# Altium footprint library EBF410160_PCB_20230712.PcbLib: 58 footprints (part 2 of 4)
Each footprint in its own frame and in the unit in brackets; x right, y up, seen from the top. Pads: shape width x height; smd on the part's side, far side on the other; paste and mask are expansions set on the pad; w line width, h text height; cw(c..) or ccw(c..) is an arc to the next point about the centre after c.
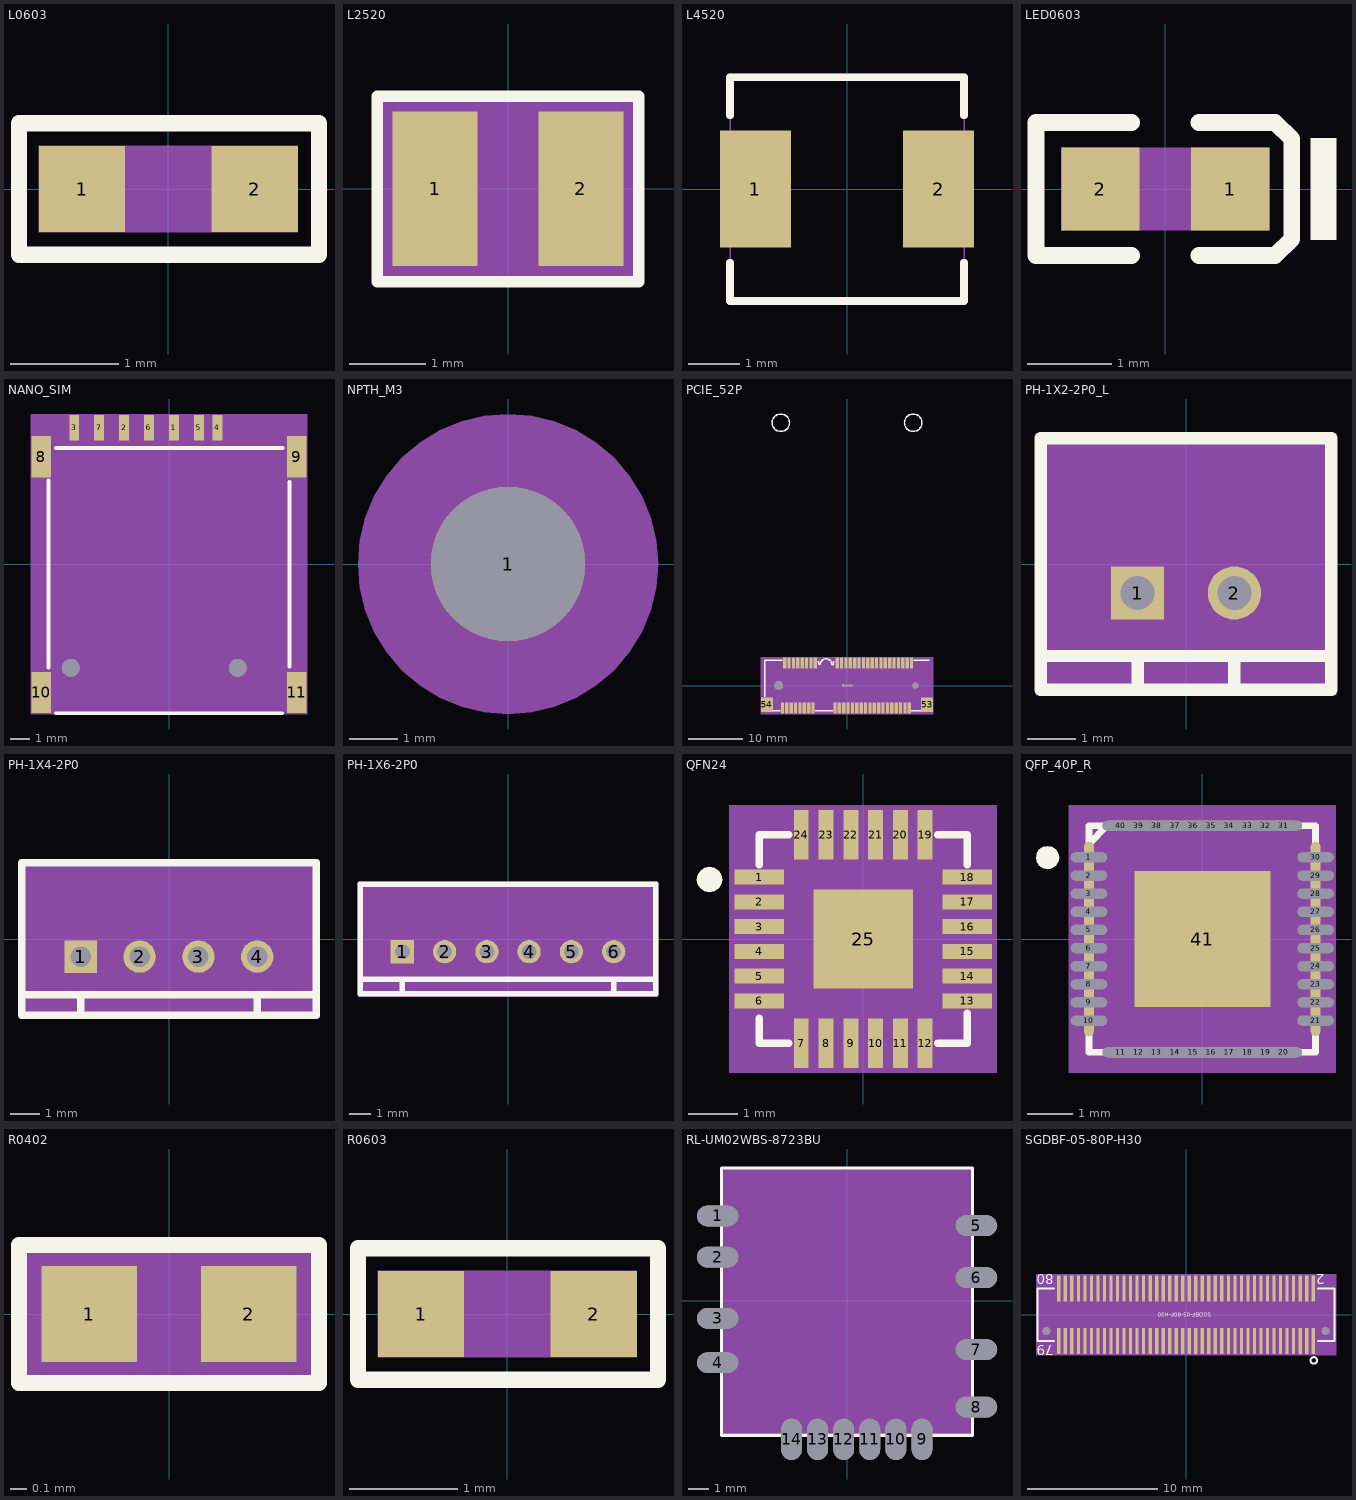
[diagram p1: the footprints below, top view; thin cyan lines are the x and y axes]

## L0603 [mil] "L0603"
pads (2):
  rect 31.5x31.5 smd: 1(-31.5,0) 2(31.5,0)
Top Overlay:
  lines w6: -54.5,-24 -54.5,24 55,24 55,-24 -54.5,-24
Top 3D Body:
  region: -47.24,-15.75 -47.24,15.75 47.24,15.75 47.24,-15.75
Mechanical 20:
  text "2" at 13.5,0 h45
  text "1" at -49.5,0 h45
3D body: height 150, standoff 0, extent -47.24,-15.75 47.24,15.75

## L2520 [mil] "L2520"
pads (2):
  rect 44x80 smd: 1(-37.75,0) 2(37.75,0)
Top Overlay:
  lines w6: -67.68,-48.15 -67.67,-48.15 67.67,-48.15 67.67,47.92 -67.68,47.92 -67.68,-48.15
Top 3D Body:
  region: -65,-45 65,-45 65,45 -65,45
Mechanical 20:
  text "2" at 37.75,-4.72 h11.81
  text "1" at -37.75,-4.72 h11.81
3D body: height 150, standoff 0, extent -65,-45 65,45

## L4520 [mm] "L4520"
pads (2):
  rect 1.4x2.3 smd: 1(-1.803,-0.002) 2(1.798,-0.002)
Top Overlay:
  lines w0.15: -2.302,-1.452 -2.302,-2.202 2.298,-2.202 2.298,-1.452 ; -2.302,1.448 -2.302,2.198 2.298,2.198 2.298,1.448
Top 3D Body:
  lines w0.025: -2.302,-2.202 2.303,-2.202 2.303,2.203 -2.302,2.203 -2.302,-2.202
Mechanical 20:
  text "1" at -1.803,-0.256 h0.64
  text "2" at 1.798,-0.256 h0.64
Top Assembly:
  lines w0.15: -2.302,-1.452 -2.302,-2.202 2.298,-2.202 2.298,-1.452 ; -2.302,1.448 -2.302,2.198 2.298,2.198 2.298,1.448

## LED0603 [mm] "LED0603"
pads (2):
  rect 0.93x0.98 smd: 1(0.77,0) 2(-0.77,0)
Top Overlay:
  dashed: 1.725,-0.6 2.025,-0.6 2.025,0.6 1.725,0.6
  lines w0.2: -0.4,-0.79 -1.535,-0.79 -1.535,0.79 -0.4,0.79 ; 0.4,-0.79 1.3,-0.79 1.5,-0.597 1.5,0.597 1.3,0.79 0.4,0.79
Top 3D Body:
  region: -1.235,-0.49 1.235,-0.49 1.235,0.49 -1.235,0.49
Mechanical 20:
  text "2" at -0.77,0.254 h0.64
  text "1" at 0.77,0.254 h0.64
3D body: height 3.81, standoff 0, extent -1.235,-0.49 1.235,0.49

## NANO_SIM [mm] "NANO_SIM"
pads (13):
  rect 0.5x1.3 smd: 1(0.25,6.94) 2(-2.29,6.94) 3(-4.83,6.94) 4(2.47,6.94) 5(1.52,6.94) 6(-1.02,6.94) 7(-3.56,6.94)
  rect 1x2.1 smd: 8(-6.5,5.46) 9(6.5,5.46) 10(-6.5,-6.54) 11(6.5,-6.54)
  round 0.9 hole 0.9 unplated: ""(-5,-5.29) ""(3.5,-5.29)
Top Overlay:
  lines w0.2: -6.145,-5.268 -6.145,4.247 ; -5.756,5.9 5.784,5.9 ; -5.749,-7.6 0,-7.6 5.749,-7.6 ; 6.145,-5.215 6.145,4.189
Top 3D Body:
  region: -7.05,-7.64 -7.05,7.64 7.05,7.64 7.05,-7.64
Mechanical 20:
  text "7" at -3.56,7.06 h0.3
  text "2" at -2.29,7.06 h0.3
  text "3" at -4.83,7.06 h0.3
  text "5" at 1.52,7.06 h0.3
  text "8" at -6.5,5.58 h0.3
  text "9" at 6.5,5.58 h0.3
  text "10" at -6.5,-6.3 h0.3
  text "11" at 6.5,-6.3 h0.3
  text "1" at 0.25,7.06 h0.3
  text "6" at -1.02,7.06 h0.3
  text "4" at 2.47,7.06 h0.3
3D body: height 3.81, standoff 0, extent -7.05,-7.64 7.05,7.64

## NPTH_M3 [mm] "NPTH_M3"
pads (1):
  round 3.2 / inner round 1.524 / far side round 3.2 hole 3.2 unplated: 1(0,0)
Top Overlay:
  text "NPTH_M3" at -0.757,0.766 h0.3
Top 3D Body:
  region: 3.11,0 3.071,0.486 2.957,0.961 2.771,1.412 2.516,1.828 2.199,2.199 1.828,2.516 1.412,2.771 0.961,2.957 0.486,3.071 0,3.11 -0.486,3.071 -0.961,2.957 -1.412,2.771 -1.551,2.686 -1.828,2.516 -2.199,2.199 -2.516,1.828 -2.771,1.412 -2.957,0.961 -3.071,0.486 -3.11,0 -3.071,-0.486 -2.957,-0.961 -2.771,-1.412 -2.516,-1.828 -2.199,-2.199 -1.828,-2.516 -1.551,-2.686 -1.412,-2.771 -0.961,-2.957 -0.486,-3.071 0,-3.11 0.486,-3.071 0.961,-2.957 1.412,-2.771 1.828,-2.516 2.199,-2.199 2.516,-1.828 2.771,-1.412 2.957,-0.961 3.071,-0.486
Mechanical 20:
  text "1" at -0.254,0 h0.64
3D body: height 3.81, standoff 0, extent -3.11,-3.11 3.11,3.11

## PCIE_52P [mm] "PCIE_52P"
pads (56):
  rect 0.6x2 smd: 1(-11.8,-4.1) 2(-11.4,4.1) 3(-11,-4.1) 4(-10.6,4.1) 5(-10.2,-4.1) 6(-9.8,4.1) 7(-9.4,-4.1) 8(-9,4.1) 9(-8.6,-4.1) 10(-8.2,4.1) 11(-7.8,-4.1) 12(-7.4,4.1) 13(-7,-4.1) 14(-6.6,4.1) 15(-6.2,-4.1) 16(-5.8,4.1) 17(-2.2,-4.1) 18(-1.8,4.1) 19(-1.4,-4.1) 20(-1,4.1) 21(-0.6,-4.1) 22(-0.2,4.1) 23(0.2,-4.1) 24(0.6,4.1) 25(1,-4.1) 26(1.4,4.1) 27(1.8,-4.1) 28(2.2,4.1) 29(2.6,-4.1) 30(3,4.1) 31(3.4,-4.1) 32(3.8,4.1) 33(4.2,-4.1) 34(4.6,4.1) 35(5,-4.1) 36(5.4,4.1) 37(5.8,-4.1) 38(6.2,4.1) 39(6.6,-4.1) 40(7,4.1) 41(7.4,-4.1) 42(7.8,4.1) 43(8.2,-4.1) 44(8.6,4.1) 45(9,-4.1) 46(9.4,4.1) 47(9.8,-4.1) 48(10.2,4.1) 49(10.6,-4.1) 50(11,4.1) 51(11.4,-4.1) 52(11.8,4.1)
  rect 2.15x2.6 smd: 53(14.65,-3.5) 54(-14.65,-3.5)
  round 1.6 hole 1.6 unplated: ""(-12.5,0)
  round 1.1 hole 1.1 unplated: ""(12.5,0)
Top Overlay:
  circle w0.25: c-12.1,48.049 r1.6
  circle w0.25: c12.1,48.049 r1.6
  lines w0.25: -15,-2.011 -15,4.6 -11.869,4.6 ; -13.487,-4.6 -12.194,-4.6 ; -5.803,-4.6 -2.572,-4.6 ; -5.325,4.387 -5.165,4.387 -5.165,3.883 -4.887,3.883 cw(c-3.843,3.859) -2.8,3.859 -2.8,3.847 -2.474,3.847 -2.474,4.381 -2.29,4.381 ; 11.787,-4.6 13.477,-4.6 ; 12.237,4.6 15,4.6
  text "MINI-PCIE" at 1.097,0.152 h0.3
Top 3D Body:
  region: -15.8,-5.2 -15.8,5.2 15.8,5.2 15.8,-5.2
Mechanical 20:
  text "14" at -6.121,4.1 h0.3
  text "22" at 0.28,4.1 h0.3
  text "10" at -7.72,4.1 h0.3
  text "33" at 4.68,-4.1 h0.3
  text "1" at -11.56,-4.1 h0.3
  text "7" at -9.16,-4.1 h0.3
  text "31" at 3.88,-4.1 h0.3
  text "20" at -0.52,4.1 h0.3
  text "12" at -6.92,4.1 h0.3
  text "25" at 1.48,-4.1 h0.3
  text "23" at 0.68,-4.1 h0.3
  text "11" at -7.32,-4.1 h0.3
  text "13" at -6.521,-4.1 h0.3
  text "50" at 11.48,4.1 h0.3
  text "40" at 7.48,4.1 h0.3
  text "34" at 5.08,4.1 h0.3
  text "26" at 1.88,4.1 h0.3
  text "18" at -1.32,4.1 h0.3
  text "4" at -10.36,4.1 h0.3
  text "43" at 8.68,-4.1 h0.3
  text "37" at 6.279,-4.1 h0.3
  text "35" at 5.48,-4.1 h0.3
  text "29" at 3.08,-4.1 h0.3
  text "27" at 2.28,-4.1 h0.3
  text "21" at -0.12,-4.1 h0.3
  text "15" at -5.72,-4.1 h0.3
  text "9" at -8.36,-4.1 h0.3
  text "54" at -14.17,-3.5 h0.3
  text "53" at 15.13,-3.5 h0.3
  text "8" at -8.76,4.1 h0.3
  text "41" at 7.88,-4.1 h0.3
  text "39" at 7.08,-4.1 h0.3
  text "52" at 12.28,4.1 h0.3
  text "24" at 1.08,4.1 h0.3
  text "2" at -11.16,4.1 h0.3
  text "32" at 4.28,4.1 h0.3
  text "19" at -0.92,-4.1 h0.3
  text "44" at 9.08,4.1 h0.3
  text "46" at 9.88,4.1 h0.3
  text "30" at 3.48,4.1 h0.3
  text "28" at 2.68,4.1 h0.3
  text "5" at -9.96,-4.1 h0.3
  text "16" at -5.32,4.1 h0.3
  text "17" at -1.72,-4.1 h0.3
  text "51" at 11.88,-4.1 h0.3
  text "49" at 11.08,-4.1 h0.3
  text "47" at 10.28,-4.1 h0.3
  text "45" at 9.48,-4.1 h0.3
  text "48" at 10.68,4.1 h0.3
  text "6" at -9.56,4.1 h0.3
  text "3" at -10.76,-4.1 h0.3
  text "42" at 8.28,4.1 h0.3
  text "36" at 5.88,4.1 h0.3
  text "38" at 6.679,4.1 h0.3
Top Assembly:
  dashed: -15.8,5.2 -15.8,-5.2 15.8,-5.2 15.8,5.2
3D body: height 3.81, standoff 0, extent -15.8,-5.2 15.8,5.2

## PH-1X2-2P0_L [mm] "PH-1X2-2P0_L"
pads (2):
  rect 1.1x1.1 / inner round 1.524 / far side rect 1.1x1.1 hole 0.7: 1(-1,-0.6)
  round 1.1 / inner round 1.524 / far side round 1.1 hole 0.7: 2(1,-0.6)
Top Overlay:
  lines w0.254: -3,-1.9 3,-1.9 ; -1,-2.6 -1,-1.9 ; 1,-2.6 1,-1.9 ; -3,-2.6 3,-2.6 3,2.6 -3,2.6 -3,-2.6
Bottom Overlay:
  lines w0.6: 0,-1.1 0,-0.1
Top 3D Body:
  region: -3.1,2.7 -3.1,-2.7 3.1,-2.7 3.1,2.7
Mechanical 20:
  text "1" at -1.254,-0.6 h0.64
  text "2" at 0.746,-0.6 h0.64
Top Assembly:
  lines w0.025: -3.1,-2.7 3.1,-2.7 3.1,2.7 -3.1,2.7 -3.1,-2.7
3D body: height 3.81, standoff 0, extent -3.1,-2.7 3.1,2.7

## PH-1X4-2P0 [mm] "PH-1X4-2P0"
pads (4):
  rect 1.1x1.1 / inner round 1.524 / far side rect 1.1x1.1 hole 0.7: 1(-3,-0.6)
  round 1.1 / inner round 1.524 / far side round 1.1 hole 0.7: 2(-1,-0.6) 3(1,-0.6)
  round 1.1 hole 0.7: 4(3,-0.6)
Top Overlay:
  lines w0.254: -5,-1.9 5,-1.9 ; -3,-2.6 -3,-1.9 ; 3,-2.6 3,-1.9 ; -5,-2.6 5,-2.6 5,2.6 -5,2.6 -5,-2.6
Top 3D Body:
  region: -5.1,2.7 -5.1,-2.7 5.1,-2.7 5.1,2.7
Mechanical 20:
  text "4" at 2.594,-0.6 h1.02
  text "1" at -3.406,-0.6 h1.02
  text "2" at -1.406,-0.6 h1.02
  text "3" at 0.594,-0.6 h1.02
3D body: height 3.81, standoff 0, extent -5.1,-2.7 5.1,2.7

## PH-1X6-2P0 [mm] "PH-1X6-2P0"
pads (6):
  rect 1.1x1.1 / inner round 1.524 / far side rect 1.1x1.1 hole 0.7: 1(-5,-0.6)
  round 1.1 hole 0.7: 2(-3,-0.6) 4(1,-0.6) 6(5,-0.6)
  round 1.1 / inner round 1.524 / far side round 1.1 hole 0.7: 3(-1,-0.6) 5(3,-0.6)
Top Overlay:
  lines w0.254: -7,-1.9 7,-1.9 ; -5,-2.6 -5,-1.9 ; 5,-2.6 5,-1.9 ; -7,-2.6 -7,2.6 7,2.6 7,-2.6 -7,-2.6
Bottom Overlay:
  lines w0.5: -4,-1.1 -4,-0.1 ; -2,-1.1 -2,-0.1 ; 0,-1.1 0,-0.1 ; 2,-1.1 2,-0.1 ; 4,-1.1 4,-0.1
Top 3D Body:
  region: -7.1,2.7 -7.1,-2.7 7.1,-2.7 7.1,2.7
Mechanical 20:
  text "5" at 3,-0.854 h0.64
  text "1" at -5,-0.854 h0.64
  text "2" at -3,-0.854 h0.64
  text "4" at 1,-0.854 h0.64
  text "6" at 5,-0.854 h0.64
  text "3" at -1,-0.854 h0.64
Top Assembly:
  lines w0.025: -7.1,-2.7 7.1,-2.7 7.1,2.7 -7.1,2.7 -7.1,-2.7
3D body: height 3.81, standoff 0, extent -7.1,-2.7 7.1,2.7

## QFN24 [mm] "QFN24"
pads (25):
  rect 1x0.3 smd: 1(-2.1,1.25) 2(-2.1,0.75) 3(-2.1,0.25) 4(-2.1,-0.25) 5(-2.1,-0.75) 6(-2.1,-1.25) 13(2.1,-1.25) 14(2.1,-0.75) 15(2.1,-0.25) 16(2.1,0.25) 17(2.1,0.75) 18(2.1,1.25)
  rect 0.3x1 smd: 7(-1.25,-2.1) 8(-0.75,-2.1) 9(-0.25,-2.1) 10(0.25,-2.1) 11(0.75,-2.1) 12(1.25,-2.1) 19(1.25,2.1) 20(0.75,2.1) 21(0.25,2.1) 22(-0.25,2.1) 23(-0.75,2.1) 24(-1.25,2.1)
  rect 2x2 smd: 25(0,0)
Top Overlay:
  dashed: -3.1,1.455 -3.198,1.435 -3.28,1.38 -3.335,1.298 -3.355,1.2 -3.335,1.102 -3.317,1.075 -3.28,1.02 -3.198,0.965 -3.1,0.945 -3.002,0.965 -2.92,1.02 -2.883,1.075 -2.865,1.102 -2.845,1.2 -2.865,1.298 -2.92,1.38 -3.002,1.435
  lines w0.15: -2.1,-1.6 -2.1,-2.1 -1.5,-2.1 ; -2.1,1.5 -2.1,2.1 -1.5,2.1 ; 1.5,-2.1 2.1,-2.1 2.1,-1.5 ; 1.5,2.1 2.1,2.1 2.1,1.5
Top 3D Body:
  region: -2.7,-2.7 2.7,-2.7 2.7,2.7 -2.7,2.7
Mechanical 20:
  text "16" at 2.1,-0.055 h0.38
  text "4" at -2.1,-0.402 h0.38
  text "20" at 0.75,1.795 h0.38
  text "1" at -2.1,1.098 h0.38
  text "3" at -2.1,0.098 h0.38
  text "18" at 2.1,0.945 h0.38
  text "8" at -0.75,-2.252 h0.38
  text "6" at -2.1,-1.402 h0.38
  text "12" at 1.25,-2.405 h0.38
  text "5" at -2.1,-0.902 h0.38
  text "10" at 0.25,-2.405 h0.38
  text "7" at -1.25,-2.252 h0.38
  text "15" at 2.1,-0.555 h0.38
  text "9" at -0.25,-2.252 h0.38
  text "14" at 2.1,-1.055 h0.38
  text "11" at 0.75,-2.405 h0.38
  text "25" at 0,-0.305 h0.38
  text "19" at 1.25,1.795 h0.38
  text "24" at -1.25,1.795 h0.38
  text "17" at 2.1,0.445 h0.38
  text "2" at -2.1,0.598 h0.38
  text "21" at 0.25,1.795 h0.38
  text "13" at 2.1,-1.555 h0.38
  text "23" at -0.75,1.795 h0.38
  text "22" at -0.25,1.795 h0.38
Top Assembly:
  lines w0.2: -2.05,-2.05 2.05,-2.05 2.05,2.05 -2.05,2.05 -2.05,-2.05
3D body: height 3.81, standoff 0, extent -2.7,-2.7 2.7,2.7

## QFP_40P_R [mil] "QFP_40P_R"
pads (41):
  oval 8.66x27.17 smd: 1(-98.43,70.87) 2(-98.43,55.12) 3(-98.43,39.37) 4(-98.43,23.62) 5(-98.43,7.87) 6(-98.43,-7.87) 7(-98.43,-23.62) 8(-98.43,-39.37) 9(-98.43,-55.12) 10(-98.43,-70.87) 21(98.43,-70.87) 22(98.43,-55.12) 23(98.43,-39.37) 24(98.43,-23.62) 25(98.43,-7.87) 26(98.43,7.87) 27(98.43,23.62) 28(98.43,39.37) 29(98.43,55.12) 30(98.43,70.87)
  oval 27.17x8.66 smd: 11(-70.87,-98.43) 12(-55.12,-98.43) 13(-39.37,-98.43) 14(-23.62,-98.43) 15(-7.87,-98.43) 16(7.87,-98.43) 17(23.62,-98.43) 18(39.37,-98.43) 19(55.12,-98.43) 20(70.87,-98.43) 31(70.87,98.43) 32(55.12,98.43) 33(39.37,98.43) 34(23.62,98.43) 35(7.87,98.43) 36(-7.87,98.43) 37(-23.62,98.43) 38(-39.37,98.43) 39(-55.12,98.43) 40(-70.87,98.43)
  rect 118.11x118.11 smd: 41(0,0)
Top Overlay:
  dashed: -127.25,77.81 -130.51,79.98 -134.35,80.75 -138.19,79.98 -141.45,77.81 -143.62,74.55 -143.88,73.26 -144.39,70.71 -143.62,66.87 -141.45,63.62 -138.19,61.44 -134.35,60.68 -131.8,61.18 -130.51,61.44 -127.25,63.62 -125.08,66.87 -124.32,70.71 -125.08,74.55
  lines w1: -98.43,-98.43 -98.43,98.43 98.43,98.43 98.43,-98.43 -98.43,-98.43
  lines w5.91: -98.43,-82.68 -98.43,-98.43 -82.68,-98.43 ; 82.68,-98.43 98.43,-98.43 98.43,-82.68 ; 82.68,98.43 98.43,98.43 98.43,82.68 ; -98.43,82.68 -82.68,98.43 -98.43,98.43 -98.43,82.68
Top Courtyard:
  dashed: -116.14,-116.14 116.14,-116.14 116.14,116.14 -116.14,116.14
Top 3D Body:
  region: -116.14,-116.14 116.14,-116.14 116.14,116.14 -116.14,116.14
Mechanical 20:
  text "21" at 87.11,-82.18 h20
  text "38" at -50.68,87.12 h20
  text "8" at -104.09,-45.03 h20
  text "3" at -104.09,33.71 h20
  text "1" at -104.09,65.21 h20
  text "2" at -104.09,49.46 h20
  text "4" at -104.09,17.96 h20
  text "5" at -104.09,2.21 h20
  text "6" at -104.09,-13.53 h20
  text "7" at -104.09,-29.27 h20
  text "9" at -104.09,-60.77 h20
  text "10" at -109.74,-82.18 h20
  text "30" at 87.11,59.56 h20
  text "18" at 28.06,-109.74 h20
  text "17" at 12.3,-109.74 h20
  text "16" at -3.44,-109.74 h20
  text "15" at -19.18,-109.74 h20
  text "19" at 43.8,-109.74 h20
  text "31" at 59.56,87.11 h20
  text "36" at -19.18,87.12 h20
  text "37" at -34.93,87.11 h20
  text "32" at 43.8,87.12 h20
  text "41" at -11.31,-11.31 h20
  text "33" at 28.06,87.12 h20
  text "34" at 12.3,87.11 h20
  text "13" at -50.68,-109.74 h20
  text "20" at 59.56,-109.74 h20
  text "14" at -34.93,-109.74 h20
  text "25" at 87.12,-19.18 h20
  text "39" at -66.43,87.12 h20
  text "24" at 87.11,-34.93 h20
  text "23" at 87.12,-50.68 h20
  text "22" at 87.12,-66.43 h20
  text "27" at 87.11,12.3 h20
  text "26" at 87.12,-3.44 h20
  text "29" at 87.12,43.8 h20
  text "40" at -82.18,87.11 h20
  text "11" at -82.18,-109.74 h20
  text "28" at 87.12,28.06 h20
  text "12" at -66.43,-109.74 h20
  text "35" at -3.44,87.12 h20
Top Assembly:
  lines w1: -98.43,90.55 -90.55,98.43 ; -98.43,-98.43 -98.43,98.43 98.43,98.43 98.43,-98.43 -98.43,-98.43
3D body: height 150, standoff 0, extent -116.14,-116.14 116.14,116.14

## R0402 [mm] "R0402"
pads (2):
  rect 0.599x0.599 smd: 1(-0.5,0) 2(0.5,0)
Top Overlay:
  lines w0.102: -0.94,-0.432 -0.94,0.432 0.94,0.432 0.94,-0.432 -0.94,-0.432
Top 3D Body:
  region: 0.94,0.432 0.94,-0.432 -0.94,-0.432 -0.94,0.432
Mechanical 20:
  text "2" at 0.246,0 h0.64
  text "1" at -0.754,0 h0.64
Top Assembly:
  dashed: -0.94,-0.432 -0.94,0.432 0.94,0.432 0.94,-0.432
3D body: height 3.81, standoff 0, extent -0.94,-0.432 0.94,0.432

## R0603 [mil] "R0603"
pads (2):
  rect 31.5x31.5 smd: 1(-31.5,0) 2(31.5,0)
Top Overlay:
  lines w6: -54.5,-24 -54.5,24 55,24 55,-24 -54.5,-24
Top 3D Body:
  region: -47.24,-15.75 -47.24,15.75 47.24,15.75 47.24,-15.75
Mechanical 20:
  text "2" at 31.5,18 h45
  text "1" at -31.5,18 h45
3D body: height 150, standoff 0, extent -47.24,-15.75 47.24,15.75

## RL-UM02WBS-8723BU [mm] "RL-UM02WBS-8723BU"
pads (14):
  oval 2x1 smd: 1(-6.3,4.122) 2(-6.3,2.122) 3(-6.3,-0.858) 4(-6.3,-3.018) 5(6.3,3.652) 6(6.3,1.122) 7(6.3,-2.378) 8(6.3,-5.178)
  oval 1x2 smd: 9(3.65,-6.748) 10(2.38,-6.748) 11(1.11,-6.748) 12(-0.16,-6.748) 13(-1.43,-6.748) 14(-2.7,-6.748)
Top Overlay:
  lines w0.15: -6.1,-6.548 -6.1,6.452 6.1,6.452 6.1,-6.548 -6.1,-6.548
Top 3D Body:
  region: -6.096,-6.452 6.096,-6.452 6.096,6.452 -6.096,6.452
Mechanical 20:
  text "5" at 6.554,3.652 h0.64
  text "1" at -6.046,4.122 h0.64
  text "8" at 6.554,-5.178 h0.64
  text "2" at -6.046,2.122 h0.64
  text "7" at 6.554,-2.378 h0.64
  text "6" at 6.554,1.122 h0.64
  text "4" at -6.046,-3.018 h0.64
  text "10" at 2.888,-6.748 h0.64
  text "9" at 3.904,-6.748 h0.64
  text "3" at -6.046,-0.858 h0.64
  text "12" at 0.348,-6.748 h0.64
  text "13" at -0.922,-6.748 h0.64
  text "14" at -2.192,-6.748 h0.64
  text "11" at 1.618,-6.748 h0.64
3D body: height 3.81, standoff 0, extent -6.096,-6.452 6.096,6.452

## SGDBF-05-80P-H30 [mm] "SGDBF-05-80P-H30"
pads (82):
  rect 0.25x2 smd: 1(9.75,-2) 2(9.75,2) 3(9.25,-2) 4(9.25,2) 5(8.75,-2) 6(8.75,2) 7(8.25,-2) 8(8.25,2) 9(7.75,-2) 10(7.75,2) 11(7.25,-2) 12(7.25,2) 13(6.75,-2) 14(6.75,2) 15(6.25,-2) 16(6.25,2) 17(5.75,-2) 18(5.75,2) 19(5.25,-2) 20(5.25,2) 21(4.75,-2) 22(4.75,2) 23(4.25,-2) 24(4.25,2) 25(3.75,-2) 26(3.75,2) 27(3.25,-2) 28(3.25,2) 29(2.75,-2) 30(2.75,2) 31(2.25,-2) 32(2.25,2) 33(1.75,-2) 34(1.75,2) 35(1.25,-2) 36(1.25,2) 37(0.75,-2) 38(0.75,2) 39(0.25,-2) 40(0.25,2) 41(-0.25,-2) 42(-0.25,2) 43(-0.75,-2) 44(-0.75,2) 45(-1.25,-2) 46(-1.25,2) 47(-1.75,-2) 48(-1.75,2) 49(-2.25,-2) 50(-2.25,2) 51(-2.75,-2) 52(-2.75,2) 53(-3.25,-2) 54(-3.25,2) 55(-3.75,-2) 56(-3.75,2) 57(-4.25,-2) 58(-4.25,2) 59(-4.75,-2) 60(-4.75,2) 61(-5.25,-2) 62(-5.25,2) 63(-5.75,-2) 64(-5.75,2) 65(-6.25,-2) 66(-6.25,2) 67(-6.75,-2) 68(-6.75,2) 69(-7.25,-2) 70(-7.25,2) 71(-7.75,-2) 72(-7.75,2) 73(-8.25,-2) 74(-8.25,2) 75(-8.75,-2) 76(-8.75,2) 77(-9.25,-2) 78(-9.25,2) 79(-9.75,-2) 80(-9.75,2)
  round 0.6 hole 0.6 unplated: ""(-10.7,-1.25) ""(10.7,-1.25)
Top Overlay:
  circle w0.15: c9.8,-3.5 r0.25
  lines w0.15: -10.1,-2 -11.4,-2 -11.4,2 -10.1,2 ; 10.1,-2 11.4,-2 11.4,2 10.1,2
  text "79" at -10.132,-2.356 h0.76
  text "2" at 10.62,3.105 h0.76
  text "80" at -10.132,3.105 h0.76
  text "SGDBF-05-80P-H30" at 1.951,0.152 h0.3
Top 3D Body:
  region: 11.5,-3.1 11.5,3.1 -11.5,3.1 -11.5,-3.1
Mechanical 20:
  text "34" at 2.258,2 h0.64
  text "32" at 2.758,2 h0.64
  text "28" at 3.758,2 h0.64
  text "36" at 1.758,2 h0.64
  text "38" at 1.258,2 h0.64
  text "45" at -0.742,-2 h0.64
  text "52" at -2.242,2 h0.64
  text "50" at -1.742,2 h0.64
  text "48" at -1.242,2 h0.64
  text "46" at -0.742,2 h0.64
  text "42" at 0.258,2 h0.64
  text "27" at 3.758,-2 h0.64
  text "25" at 4.258,-2 h0.64
  text "51" at -2.242,-2 h0.64
  text "53" at -2.742,-2 h0.64
  text "10" at 8.258,2 h0.64
  text "49" at -1.742,-2 h0.64
  text "15" at 6.758,-2 h0.64
  text "61" at -4.742,-2 h0.64
  text "29" at 3.258,-2 h0.64
  text "13" at 7.258,-2 h0.64
  text "8" at 8.504,2 h0.64
  text "31" at 2.758,-2 h0.64
  text "47" at -1.242,-2 h0.64
  text "17" at 6.258,-2 h0.64
  text "37" at 1.258,-2 h0.64
  text "59" at -4.242,-2 h0.64
  text "39" at 0.758,-2 h0.64
  text "11" at 7.758,-2 h0.64
  text "72" at -7.242,2 h0.64
  text "74" at -7.742,2 h0.64
  text "1" at 10.004,-2 h0.64
  text "23" at 4.758,-2 h0.64
  text "33" at 2.258,-2 h0.64
  text "69" at -6.742,-2 h0.64
  text "71" at -7.242,-2 h0.64
  text "73" at -7.742,-2 h0.64
  text "75" at -8.242,-2 h0.64
  text "77" at -8.742,-2 h0.64
  text "79" at -9.242,-2 h0.64
  text "2" at 10.004,2 h0.64
  text "12" at 7.758,2 h0.64
  text "26" at 4.258,2 h0.64
  text "40" at 0.758,2 h0.64
  text "54" at -2.742,2 h0.64
  text "58" at -3.742,2 h0.64
  text "64" at -5.242,2 h0.64
  text "70" at -6.742,2 h0.64
  text "76" at -8.242,2 h0.64
  text "78" at -8.742,2 h0.64
  text "80" at -9.242,2 h0.64
  text "68" at -6.242,2 h0.64
  text "35" at 1.758,-2 h0.64
  text "63" at -5.242,-2 h0.64
  text "41" at 0.258,-2 h0.64
  text "65" at -5.742,-2 h0.64
  text "67" at -6.242,-2 h0.64
  text "66" at -5.742,2 h0.64
  text "62" at -4.742,2 h0.64
  text "44" at -0.242,2 h0.64
  text "30" at 3.258,2 h0.64
  text "60" at -4.242,2 h0.64
  text "55" at -3.242,-2 h0.64
  text "57" at -3.742,-2 h0.64
  text "56" at -3.242,2 h0.64
  text "43" at -0.242,-2 h0.64
  text "9" at 8.004,-2 h0.64
  text "5" at 9.004,-2 h0.64
  text "3" at 9.504,-2 h0.64
  text "7" at 8.504,-2 h0.64
  text "19" at 5.758,-2 h0.64
  text "21" at 5.258,-2 h0.64
  text "20" at 5.758,2 h0.64
  text "18" at 6.258,2 h0.64
  text "16" at 6.758,2 h0.64
  text "14" at 7.258,2 h0.64
  text "4" at 9.504,2 h0.64
  text "22" at 5.258,2 h0.64
  text "24" at 4.758,2 h0.64
  text "6" at 9.004,2 h0.64
Top Assembly:
  lines w0.15: -11.4,-2 -11.4,2 11.4,2 11.4,-2 -11.4,-2
3D body: height 3.81, standoff 0, extent -11.5,-3.1 11.5,3.1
